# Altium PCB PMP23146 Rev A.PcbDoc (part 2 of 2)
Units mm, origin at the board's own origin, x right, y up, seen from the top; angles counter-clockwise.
Board outline 35 x 30 mm, 4 copper layers (Top Layer, Int1 (GND), Int2 (PWR), Bottom Layer), stack 0.912 mm thick; 72 components, 51 nets, 255 pads, 53 vias.
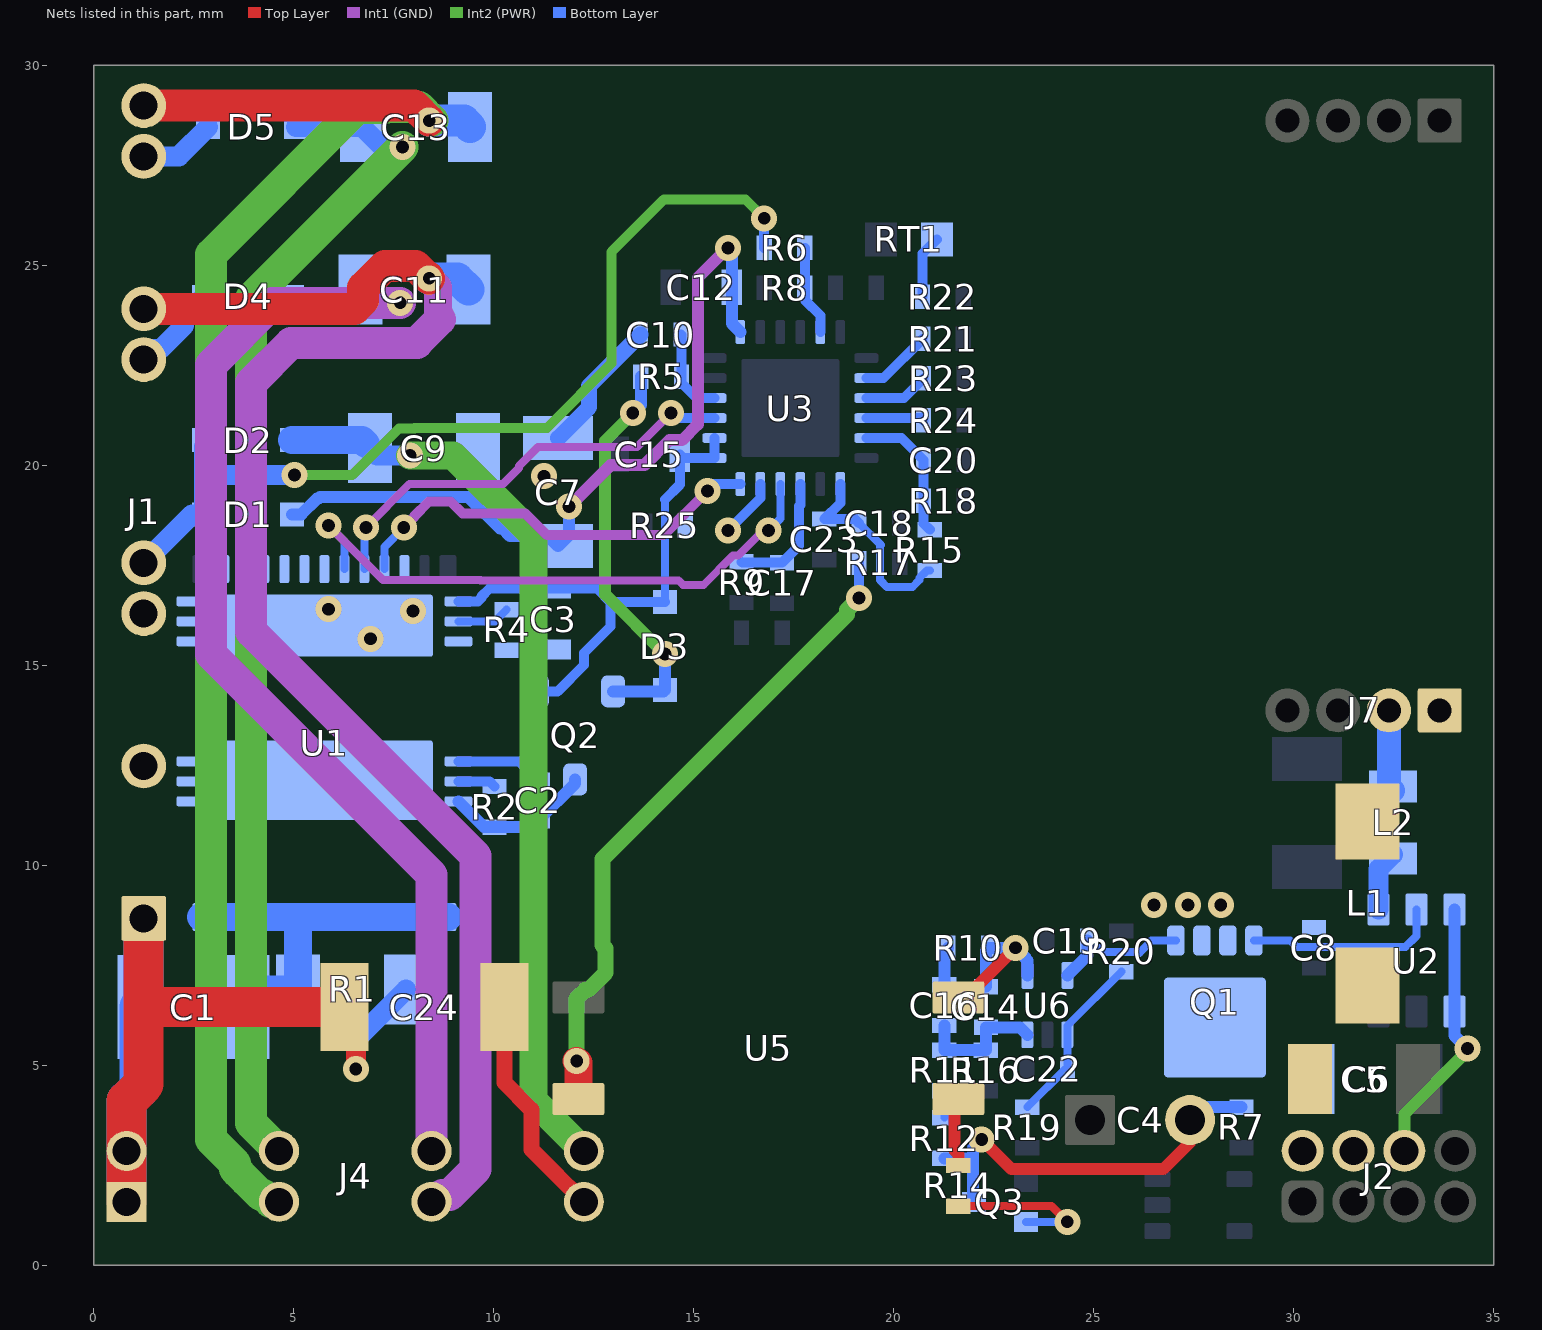
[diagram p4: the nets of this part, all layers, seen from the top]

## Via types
v1: diameter 0.65, hole 0.32, Top Layer to Bottom Layer, 44 vias
v2: diameter 0.5, hole 0.2, Top Layer to Bottom Layer, 5 vias
v3: diameter 0.65, hole 0.32, Top Layer to Bottom Layer, tented bottom, 4 vias

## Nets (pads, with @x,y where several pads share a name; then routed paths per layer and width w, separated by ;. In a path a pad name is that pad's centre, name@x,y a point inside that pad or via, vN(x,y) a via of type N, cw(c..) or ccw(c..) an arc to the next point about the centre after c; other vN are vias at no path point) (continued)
NetC1_2: C1.2 R1.1 U1.1 U1.2 U1.3 U1.4 U1.5 U1.6 U1.7 U1.8 U1.9 U1.10 U1.11 U1.12 U1.13 | length 9.5
  Bottom Layer w0.7: U1.13@2.673,8.707 U1.12@3.261,8.707 U1.11@3.761,8.707 U1.10@4.261,8.707 U1.9@4.761,8.707 U1.8@5.261,8.707 ; C1.2@3.837,6.46 4.276,6.899 R1.1@5.107,6.899 5.107,8.553 U1.8@5.261,8.707 ; U1.1@8.848,8.707 U1.2@8.261,8.707 U1.3@7.761,8.707 U1.4@7.261,8.707 U1.5@6.761,8.707 U1.6@6.261,8.707 U1.7@5.761,8.707 U1.8@5.261,8.707
NetC2_1: C2.1 U1.36 | length 2.2
  Bottom Layer w0.25: U1.36@9.111,12.602 10.628,12.602 C2.1@11.099,12.131
NetC14_1: C14.1 R10.2 U5.3 U6.4 | length 4.4
  Top Layer w0.3: U5.3@21.61,6.699 21.797,6.699 v1(23.039,7.941)
  Bottom Layer w0.3: C14.1@22.3,6.968 22.3,7.873 R10.2@22.369,7.941 v1(23.039,7.941) 23.286,7.695 23.286,7.673 23.334,7.624 U6.4@23.334,7.246
NetC14_2: C14.2 C16.1 R11.2 R16.2 U6.3 | length 3.3
  Bottom Layer w0.3: C16.1@21.26,5.998 R11.2@21.26,5.382 R16.2@22.297,5.382 22.297,5.574 ; R16.2@22.299,5.572 22.297,5.574 ; U6.3@23.334,5.766 23.149,5.952 C14.2@22.3,5.952 22.297,5.948 22.297,5.574
NetC16_2: C16.2 R10.1 | length 1
  Bottom Layer w0.3: C16.2@21.26,7.014 21.26,7.849 R10.1@21.353,7.941
NetC17_1: C17.1 R9.2 U3.9 | length 3.2
  Bottom Layer w0.25: R9.2@16.19,17.591 16.212,17.569 C17.1@17.202,17.569 17.63,17.997 17.63,18.982 17.661,19.013 U3.9@17.661,19.534
NetC20_2: C20.2 R15.1 R18.2 U3.5 | length 3.5
  Bottom Layer w0.25: U3.5@19.311,20.684 20.191,20.684 C20.2@20.741,20.134 R18.2@20.741,19.119 20.741,18.55 R15.1@20.899,18.392
NetC22_1: C22.1 R19.1 R20.2 U6.1 | length 4.4
  Bottom Layer w0.2: R19.1@23.334,3.957 24.288,4.911 C22.1@24.342,4.911 24.342,5.758 U6.1@24.334,5.766 24.334,5.991 R20.2@25.686,7.342
NetD3_1: D3.1 Q2.2 R5.2 | length 10.1
  Int2 (PWR) w0.3: v1(13.47,21.307) 12.78,20.617 12.78,16.778 v1(14.276,15.282)
  Bottom Layer w0.3: Q2.2@12.981,14.35 14.245,14.35 D3.1@14.276,14.381 v1(14.276,15.282) ; v1(13.47,21.307) 13.672,21.509 R5.2@13.672,22.218
NetD4_2: D4.2 J1.12 | length 2.3
  Bottom Layer w0.5: J1.12@1.245,22.646 1.505,22.906 1.663,22.906 2.255,23.498 2.255,23.714 D4.2@2.757,24.216
NetD5_2: D5.2 J1.16 | length 1.9
  Bottom Layer w0.5: J1.16@1.245,27.726 2.124,27.726 D5.2@2.857,28.46
NetJ7_1: J7.1 J7.2 L1.1 L2.1 | length 2
  Bottom Layer w0.6: J7.2@32.375,13.875 32.375,11.975 L2.1@32.477,11.873
NetQ1_4: Q1.4 U2.5 | length 4.9
  Bottom Layer w0.2: Q1.4@29,8.122 29.907,8.122 30.071,7.959 32.784,7.959 33.062,8.237 U2.5@33.062,8.897
NetQ3_2: Q3.2 R14.2 | length 3.9
  Top Layer w0.2: R14.2@21.61,1.482 23.942,1.482 v3(24.334,1.09)
  Bottom Layer w0.2: Q3.2@23.298,1.09 v3(24.334,1.09)
NetR2_2: R2.2 U1.37 | length 1
  Bottom Layer w0.25: U1.37@9.111,12.102 9.886,12.102 R2.2@10.015,11.973
NetR4_2: R4.2 U1.34 | length 1.3
  Bottom Layer w0.2: U1.34@9.111,16.102 10.023,16.102 R4.2@10.315,16.393
NetR6_1: R6.1 R8.2 U3.23 | length 2.3
  Bottom Layer w0.25: R6.1@17.772,25.438 R8.2@17.772,24.444 17.772,24.136 18.161,23.747 U3.23@18.161,23.334
NetR11_1: R11.1 R12.2 | length 0.7
  Bottom Layer w0.2: R12.2@21.26,3.692 R11.1@21.26,4.366
NetR14_1: R14.1 U5.1 | length 1.7
  Top Layer w0.3: R14.1@21.61,2.498 21.61,2.777 21.519,2.868 21.519,4.068 U5.1@21.61,4.159
NetR17_2: R17.2 U5.6 | length 16.5
  Top Layer w0.7: v1(12.069,5.11) 12.11,5.069 U5.6@12.11,4.159
  Int2 (PWR) w0.4: v1(12.069,5.11) 12.069,6.674 12.293,6.897 12.37,6.897 12.794,7.322 12.794,7.923 12.712,8.005 12.712,10.157 18.831,16.276 18.831,16.39 v1(19.128,16.687)
  Bottom Layer w0.25: v1(19.128,16.687) R17.2@19.128,17.561
NetR21_2: R21.2 U3.2 | length 1.8
  Bottom Layer w0.25: U3.2@19.311,22.184 19.741,22.184 R21.2@20.719,23.162
NetR22_2: R22.2 RT1.2 | length 1.6
  Bottom Layer w0.25: R22.2@20.716,24.216 20.716,25.295 RT1.2@21.075,25.654
NetR23_2: R23.2 U3.3 | length 1.6
  Bottom Layer w0.25: U3.3@19.311,21.684 20.25,21.684 R23.2@20.741,22.176
NetR24_2: R24.2 U3.4 | length 1.5
  Bottom Layer w0.25: U3.4@19.311,21.184 20.686,21.184 R24.2@20.741,21.129
P12V: C9.1 D2.1 J4.20 | length 22.9
  Int2 (PWR) w0.7: v1(7.904,20.25) 8.981,20.25 10.984,18.247 10.984,4.123 J4.20@12.247,2.86
  Bottom Layer w0.5: C9.1@6.798,20.533 C9.1@6.896,20.434 7.08,20.25 v1(7.904,20.25)
  Bottom Layer w0.7: D2.1@4.957,20.632 5.373,20.633 6.698,20.632 C9.1@6.798,20.533
P12V_ISO1: C13.1 D5.1 J4.8 | length 29.8
  Int2 (PWR) w0.8: J4.8@4.627,2.86 3.924,3.563 3.924,24.173 v3(7.711,27.96)
  Bottom Layer w0.5: D5.1@5.057,28.46 C13.1@6.707,28.46 7.207,27.96 v3(7.711,27.96)
P12V_ISO1_RTN: C13.2 J1.17 J4.7 | length 40.2
  Top Layer w0.8: J1.17@1.245,28.996 8.002,28.996 v1(8.382,28.617)
  Int2 (PWR) w0.7: v1@8.389,28.625 8.397,28.617 v1@8.468,28.617
  Int2 (PWR) w0.8: J4.7@4.627,1.59 4.408,1.59 4.238,1.76 4.172,1.76 3.804,2.128 3.658,2.273 3.595,2.337 3.535,2.397 3.527,2.404 3.527,2.546 2.924,3.149 2.924,25.268 6.597,28.941 7.278,28.941 7.296,28.96 8.125,28.96 v1@8.468,28.617
  Bottom Layer w0.8: v1(8.382,28.617) 9.25,28.617 C13.2@9.407,28.46
P12V_ISO2: C11.1 D4.1 J4.14 | length 30.4
  Top Layer w0.2: J4.14@8.23,2.848 8.425,2.848 J4.14@8.437,2.86
  Int1 (GND) w0.8: v1(7.657,24.066) 4.48,24.066 2.924,22.511 2.924,15.28 8.437,9.767 J4.14@8.437,2.86
  Bottom Layer w0.5: D4.1@4.957,24.216 6.484,24.216 C11.1@6.665,24.397 6.995,24.066 v1(7.657,24.066)
P12V_ISO2_RTN: C11.2 J1.13 J4.13 | length 39.2
  Top Layer w0.2: J4.13@8.234,1.59 J4.13@8.437,1.59
  Top Layer w0.8: J1.13@1.245,23.916 6.515,23.916 6.732,24.134 6.732,24.449 7.274,24.991 8.04,24.991 8.325,24.707 8.352,24.707 v1(8.382,24.677)
  Int1 (GND) w0.7: v1@8.343,24.724 8.607,24.46 8.607,23.804 8.657,23.754 8.657,23.652
  Int1 (GND) w0.8: J4.13@8.437,1.59 8.543,1.59 8.713,1.76 8.893,1.76 9.537,2.404 9.537,10.239 3.924,15.852 3.924,22.06 4.931,23.066 8.071,23.066 8.657,23.652
  Bottom Layer w0.8: v1(8.382,24.677) 9.085,24.677 C11.2@9.365,24.397
P13: C3.2 C15.2 D3.2 Q2.1 U1.33 U3.13 U3.14 | length 14
  Bottom Layer w0.2: D3.2@14.276,16.581 14.276,19.146
  Bottom Layer w0.25: U1.33@9.111,16.602 9.598,16.602 9.685,16.689 9.685,16.719 9.889,16.922 C3.2@11.484,16.922 12.573,16.922 12.915,16.581 ; Q2.1@11.081,14.35 11.594,14.35 12.254,15.01 12.254,15.31 12.915,15.971 12.915,16.581 ; D3.2@14.276,16.581 12.915,16.581 ; 14.276,19.146 14.648,19.518 C15.2@14.648,20.274 14.738,20.184 U3.13@15.511,20.184 U3.14@15.511,20.684
PWMH: U1.28 U3.15 | length 11
  Int1 (GND) w0.2: v1(6.798,18.449) 7.883,19.534 10.225,19.534 10.628,19.937 10.628,19.988 11.099,20.459 13.576,20.459 v1(14.424,21.307)
  Bottom Layer w0.2: U1.28@6.761,17.407 6.761,18.412 v1(6.798,18.449)
  Bottom Layer w0.25: v1(14.424,21.307) 14.547,21.184 U3.15@15.511,21.184
PWML: U1.29 U3.12 | length 10.8
  Int1 (GND) w0.25: v1(7.746,18.449) 7.996,18.699 7.996,18.719 8.377,19.099 8.915,19.099 9.212,18.803 10.779,18.803 11.327,18.255 14.232,18.255 v1(15.336,19.359)
  Bottom Layer w0.2: U1.29@7.261,17.407 7.261,17.964 v1(7.746,18.449)
  Bottom Layer w0.25: v1(15.336,19.359) 15.511,19.534 U3.12@16.161,19.534
PWRGND: C3.1 C7.2 C9.2 C10.1 C24.2 J1.7 J4.19 R4.1 R25.1 U1.17 U1.18 U1.19 U1.21 U1.22 U1.23 U1.24 U1.25 U1.26 U1.30 U1.35 U1.40 U3.11 | length 10.6
  Top Layer w0.4: C24.2@10.261,6.46 10.258,6.457 10.258,4.575 10.937,3.896 10.937,2.9 11.347,2.49 11.347,2.487 11.874,1.96 11.877,1.96 J4.19@12.247,1.59
  Bottom Layer w0.25: v1(15.848,18.37) 16.661,19.183 U3.11@16.661,19.534
  Bottom Layer w0.4: C7.2@11.603,20.679 12.378,21.454 12.378,21.988 C10.1@13.662,23.272
  other v1: 6.911,15.666 7.977,16.361 5.861,16.404 11.253,19.729
REF: C18.2 C23.1 R15.2 U3.7 | length 5.1
  Bottom Layer w0.2: C18.2@19.128,18.555 19.674,18.01 19.654,17.99 19.654,17.132 19.829,16.956 20.459,16.956 20.635,17.132 20.635,17.184 20.827,17.376 R15.2@20.899,17.376
  Bottom Layer w0.25: U3.7@18.661,19.534 18.661,19.058 C23.1@18.26,18.657 19.026,18.657 C18.2@19.128,18.555
RUN: U1.27 U3.10 | length 14.7
  Int1 (GND) w0.2: v3(5.861,18.499) 7.228,17.132 9.662,17.132 9.666,17.128 14.615,17.128 14.727,17.016 15.245,17.016 15.974,17.745 16.107,17.745 16.732,18.37 v1(16.86,18.37)
  Bottom Layer w0.2: v3(5.861,18.499) 6.261,18.099 U1.27@6.261,17.407 ; v1(16.86,18.37) 17.161,18.671 U3.10@17.161,19.534
SWS: C10.2 R5.1 U3.16 | length 2.2
  Bottom Layer w0.25: C10.2@14.678,23.272 14.688,23.262 R5.1@14.688,22.218 14.688,22.06 15.063,21.684 U3.16@15.511,21.684
VAUX: D1.2 D2.2 J1.8 R6.2 | length 23.3
  Int2 (PWR) w0.25: v3(5.011,19.758) 6.457,19.758 7.624,20.925 8.009,20.925 8.018,20.934 11.325,20.934 12.942,22.552 12.942,25.34 14.246,26.645 14.34,26.645 14.341,26.646 16.289,26.646 v1(16.756,26.179)
  Bottom Layer w0.25: R6.2@16.756,25.438 v1(16.756,26.179)
  Bottom Layer w0.5: J1.8@1.245,17.566 2.448,18.769 D1.2@2.757,18.769 2.757,19.858 ; D2.2@2.811,20.533 2.757,20.479 2.757,19.858 ; v3(5.011,19.758) 2.857,19.758 2.757,19.858
VDCIN: C1.1 C24.1 J1.1 J4.1 J4.2 R1.2 | length 23.8
  Top Layer w0.5: C24.1@6.261,6.46 6.546,6.174 v1(6.546,4.911)
  Top Layer w1: J4.1@0.817,1.59 J4.2@0.817,2.86 0.817,4.104 1.245,4.532 1.245,6.46 ; J1.1@1.245,8.676 1.245,6.46 ; 1.305,6.399 1.245,6.46 ; C24.1@6.261,6.46 1.245,6.46
  Bottom Layer w0.5: v1(6.546,4.911) 6.546,5.638 R1.2@7.807,6.899
  Bottom Layer w1: J4.1@0.817,1.59 J4.2@0.817,2.86 0.817,4.104 1.137,4.424 C1.1@1.137,6.46 1.245,6.568 J1.1@1.245,8.676
VDD: C7.1 C12.1 D1.1 U3.19 | length 19.5
  Int1 (GND) w0.3: v1(11.877,18.969) 12.917,20.009 13.763,20.009 14.385,20.632 14.704,20.632 15.099,21.028 15.099,24.689 v1(15.848,25.438)
  Bottom Layer w0.3: D1.1@4.957,18.769 5.186,18.769 5.186,18.779 5.581,19.174 5.611,19.174 5.646,19.209 9.365,19.209 10.146,18.428 10.204,18.428 10.402,18.23 11.352,18.23 C7.1@11.603,17.979 11.877,18.253 v1(11.877,18.969) ; v1(15.848,25.438) 15.948,25.338 C12.1@15.948,24.449 15.948,23.547 U3.19@16.161,23.334
VOUT: C4.2 C5.2 C8.1 C19.2 J2.2 L1.2 L2.2 Q1.1 Q1.2 Q1.3 Q3.3 R7.2 R12.1 U2.4 U6.5 | length 15.2
  Top Layer w0.3: v1(22.194,3.147) 22.937,2.404 26.732,2.404 27.403,3.076 C4.2@27.403,3.636
  Bottom Layer w0.2: C19.2@24.842,7.938 25.151,7.938 25.257,7.833 26.115,7.833 26.134,7.813 26.443,8.122 Q1.1@27.05,8.122
  Bottom Layer w0.3: R12.1@21.26,2.676 21.966,2.676 21.978,2.689 ; Q3.3@21.998,1.59 21.978,1.61 21.978,2.689 ; v1(22.194,3.147) 21.978,2.931 21.978,2.689 ; U6.5@24.334,7.246 24.842,7.754 24.842,7.938 C19.2@24.842,8.122 ; C4.2@27.303,3.736 27.524,3.957 R7.2@28.688,3.957
  Bottom Layer w0.5: U2.4@32.112,8.897 32.112,9.908 L2.2@32.477,10.273
  other v1: 26.501,9.007 27.348,9.007 28.171,9.007
VOUT_OR: C6.1 J2.4 J2.6 Q1.5 Q1.6 Q1.7 Q1.8 Q1.9@28.025,5.947 U2.1 U2.6 | length 6.8
  Int2 (PWR) w0.3: J2.6@32.758,2.866 32.758,3.782 34.339,5.363 v1(34.339,5.419)
  Bottom Layer w0.3: U2.6@34.012,8.897 U2.1@34.012,6.347 34.012,5.746 v1(34.339,5.419)
VSWN: C2.2 J1.4 Q2.3 R2.1 U1.14 U1.15 U1.16 U1.38 U1.39 | length 3.7
  Bottom Layer w0.3: U1.38@9.111,11.602 9.755,10.957 R2.1@10.015,10.957 10.941,10.957 C2.2@11.099,11.115 12.031,12.047 Q2.3@12.031,12.15
pads on no net: Q1.9@27.05,5.422 Q1.9@27.7,5.422 Q1.9@27.363,5.933 Q1.9@27.363,6.809 Q1.9@28.025,6.27 Q1.9@28.35,5.422 Q1.9@28.688,5.933 Q1.9@28.688,6.809 Q1.9@29,5.422 U1.20 U2.3 U4.2 U4.4 U4.5

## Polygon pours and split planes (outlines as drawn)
GND on Bottom Layer "BOTTOM_LAYER_GND_P013" (solid, remove dead copper, pour order 13): 27.041,11.312 27.041,9.306 31.306,9.306 31.306,11.312
GND on Bottom Layer "BOTTOM_LAYER_GND_P012" (solid, remove dead copper, pour order 12): 20.974,8.287 20.974,0.13 34.957,0.13 34.957,8.287
VOUT on Bottom Layer "BOTTOM_LAYER_VOUT_P011" (solid, remove dead copper, pour order 11): 26.167,9.432 26.167,7.246 32.503,7.246 32.503,9.432
VOUT_OR on Bottom Layer "BOTTOM_LAYER_VOUT_OR_P006" (solid, remove dead copper, pour order 6): 26.663,7.263 26.663,2.246 33.452,2.246 33.452,7.263
ICGND on Bottom Layer "BOTTOM_LAYER_ICGND_P002" (solid, remove dead copper, pour order 2): 12.786,26.454 12.786,15.466 22.328,15.466 22.328,26.454
VSWN on Bottom Layer "BOTTOM_LAYER_VSWN_P001" (solid, remove dead copper, pour order 1): 0.635,13.15 0.635,11.073 9.665,11.073 9.665,13.15
PWRGND on Bottom Layer "BOTTOM_LAYER_PWRGND_P000" (solid, remove dead copper, pour order 0): 0.384,22.414 0.384,15.251 22.328,15.251 22.328,22.414
NetJ7_1 on Top Layer "TOP_LAYER_NETJ7_1_P008" (solid, remove dead copper, pour order 8): 28.95,14.423 28.95,10.157 35,10.157 35,14.423
GND on Top Layer "TOP_LAYER_GND_P014" (solid, remove dead copper, pour order 14): 20.993,8.272 20.993,0.116 34.976,0.116 34.976,8.272
VOUT on Top Layer "TOP_LAYER_VOUT_P007" (solid, remove dead copper, pour order 7): 26.053,9.397 26.053,2.225 35,2.225 35,9.397
PWRGND on Top Layer "TOP_LAYER_PWRGND_P005" (solid, remove dead copper, pour order 5): 11.877,26.455 11.877,15.467 22.365,15.467 22.365,26.455
PWRGND on Top Layer "TOP_LAYER_PWRGND_P003" (solid, remove dead copper, pour order 3): 0.089,21.334 0.089,-0.008 12.712,-0.008 12.712,21.334
GND on Int2 (PWR) "INT2_(PWR)_GND_P018" (solid, remove dead copper, pour order 18): 20.974,11.602 20.974,0.262 34.867,0.262 34.867,11.602
ISNS on Int2 (PWR) "INT2_(PWR)_ISNS_P015" (solid, remove dead copper, pour order 15): 28.904,29.984 28.904,12.738 34.965,12.738 34.965,29.984
ICGND on Int2 (PWR) "INT2_(PWR)_ICGND_P004" (solid, remove dead copper, pour order 4): 12.786,26.454 12.786,15.466 22.328,15.466 22.328,26.454
GND on Int1 (GND) "INT1_(GND)_GND_P016" (solid, remove dead copper, pour order 16): 20.974,11.602 20.974,0 35,0 35,11.602
ISNS on Int1 (GND) "INT1_(GND)_ISNS_P010" (solid, remove dead copper, pour order 10): 28.95,30.051 28.95,12.805 35.012,12.805 35.012,30.051

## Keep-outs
Int1 (GND):
  lines w0.254: 20.993,8.632 22.918,8.632 26.277,12.003
Int2 (PWR):
  lines w0.254: 20.993,8.632 22.906,8.632 26.277,12.003
Keep-Out Layer:
  text ".Layer_Name" at 14.656,-21.806 h1.52

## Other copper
Top Layer:
  text ".Layer_Name" at 14.656,-21.806 h1.52
Bottom Layer:
  text ".Layer_Name" at 14.656,-21.806 h1.52

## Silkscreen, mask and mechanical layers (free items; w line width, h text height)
Top Overlay:
  text ".Layer_Name" at 14.656,-21.806 h1.52
Bottom Overlay:
  text "PMP23146PCB Rev A" at 29,28.11 h2
  text ".Layer_Name" at 14.656,-21.806 h1.52
Top Paste:
  text ".Layer_Name" at 14.656,-21.806 h1.52
Bottom Paste:
  text ".Layer_Name" at 14.656,-21.806 h1.52
Top Solder:
  text ".Layer_Name" at 14.656,-21.806 h1.52
  text ".Layer_Name" at 14.656,-21.806 h1.52
Bottom Solder:
  text ".Layer_Name" at 14.656,-21.806 h1.52
Drill Guide:
  text ".Layer_Name" at 14.656,-21.806 h1.52
M1 Board Outline:
  the board outline again, w0.254
  text ".Layer_Name" at 14.656,-21.806 h1.52
M2 Board Dimensions:
  rectangle: 0,-6.985 3.175,-3.81
  rectangle: 3.175,-10.16 12.7,-6.985
  lines w0.178: 0,-6.985 25.4,-6.985 ; 3.175,-10.16 3.175,-3.81 ; 6.35,-10.16 6.35,-3.81 ; 12.7,-10.16 12.7,-3.81 ; 19.05,-10.16 19.05,-3.81 ; 0,-10.16 25.4,-10.16 25.4,-3.81 0,-3.81 0,-10.16
  text ".Layer_Name" at 14.656,-21.806 h1.52
M3 3D STEP Top:
  text ".Layer_Name" at 14.656,-21.806 h1.52
M4 3D STEP Bottom:
  text ".Layer_Name" at 14.656,-21.806 h1.52
M5 Assembly Top:
  lines w0.254: -7.417,-23.626 160.223,-23.626 ; -7.417,-18.462 160.274,-18.462 ; -7.417,-13.297 -7.417,-28.791 94.31,-28.791 160.274,-28.791 160.274,-13.297 -7.404,-13.297 -7.404,-28.791 32.614,-28.791 ; 55.194,-28.791 55.194,-13.297 ; 87.376,-18.462 87.376,-13.297 ; 108.712,-18.462 108.712,-13.297 ; 124.511,-28.956 124.511,-23.804
  text "COMPONENTS MARKED 'DNP' SHOULD NOT BE POPULATED." at 29.299,-8.09 h1.52
  text "ASSEMBLY VARIANT:" at 29.286,-11.024 h1.52
  text ".VariantName" at 55.601,-11.024 h1.52
  text "PCB VIEWED FROM TOP SIDE" at -5.804,-16.654 h1.52
  text "BOARD #:" at 57.099,-16.654 h1.52
  text ".PRJ_Number" at 70.955,-16.654 h1.52
  text "REV:" at 92.405,-16.654 h1.52
  text ".PCB_Rev" at 99.809,-16.654 h1.52
  text "SVN REV:" at 113.69,-16.654 h1.52
  text ".VersionControl_RevNumber" at 126.543,-16.654 h1.52
  text "TID #:" at 57.099,-21.819 h1.52
  text ".TID" at 70.955,-21.819 h1.52
  text "PLOT NAME =" at -5.804,-27.034 h1.52
  text ".plot_File_Name" at 14.656,-27.034 h1.52
  text "GENERATED    :" at 57.15,-27.034 h1.52
  text ".Print_Date" at 79.235,-27.034 h1.52
  text ".Print_Time" at 97.752,-27.034 h1.52
  text "TEXAS INSTRUMENTS" at 129.87,-27.034 h1.52
M6 Assembly Bottom:
  lines w0.254: -7.429,-18.474 160.261,-18.474 ; -7.379,-23.639 160.261,-23.639 ; 28.334,-28.969 28.334,-23.817 ; 44.133,-18.474 44.133,-13.31 ; 65.468,-18.474 65.468,-13.31 ; 97.65,-28.804 97.65,-13.31 ; 120.231,-28.804 160.249,-28.804 160.249,-13.31 -7.429,-13.31 -7.429,-28.804 58.534,-28.804 160.261,-28.804 160.261,-13.31
  text "COMPONENTS MARKED 'DNP' SHOULD NOT BE POPULATED." at 154.991,-8.077 h1.52
  text ".VariantName" at 128.473,-11.024 h1.52
  text "ASSEMBLY VARIANT:" at 154.864,-11.024 h1.52
  text ".VersionControl_RevNumber" at 26.302,-16.667 h1.52
  text "SVN REV:" at 39.154,-16.667 h1.52
  text ".PCB_Rev" at 53.035,-16.667 h1.52
  text "REV:" at 60.439,-16.667 h1.52
  text ".PRJ_Number" at 81.89,-16.667 h1.52
  text "BOARD #:" at 95.745,-16.667 h1.52
  text "PCB VIEWED FROM BOTTOM SIDE" at 158.648,-16.667 h1.52
  text ".TID" at 81.89,-21.831 h1.52
  text "TID #:" at 95.745,-21.831 h1.52
  text "TEXAS INSTRUMENTS" at 22.974,-27.047 h1.52
  text ".Print_Time" at 55.093,-27.047 h1.52
  text ".Print_Date" at 73.609,-27.047 h1.52
  text "GENERATED    :" at 95.694,-27.047 h1.52
  text ".plot_File_Name" at 138.189,-27.047 h1.52
  text "PLOT NAME =" at 158.648,-27.047 h1.52
M9 Title Sheet:
  drawing of 57 lines, arcs and shapes, not listed
  text "1" at 18.792,204.127 h1.78
  text "2" at 82.182,204.127 h1.78
  text "3" at 145.411,204.127 h1.78
  text "4" at 209.08,204.127 h1.78
  text "5" at 272.555,204.127 h1.78
  text "6" at 336.182,204.127 h1.78
  text "A" at -10.579,175.095 h1.78
  text "A" at 365.341,175.095 h1.78
  text "B" at -10.579,114.643 h1.78
  text "B" at 365.341,114.643 h1.78
  text "C" at -10.579,54.318 h1.78
  text "C" at 365.341,54.318 h1.78
  text "PROJECT TITLE:" at 288.125,7.048 h1.14
  text ".PRJ_Title" at 289.395,3.662 h1.78
  text "DESIGNED FOR:" at 288.125,-0.597 h1.14
  text ".PRJ_Customer" at 289.395,-4.153 h1.78
  text "D" at -10.579,-5.88 h1.78
  text "D" at 365.341,-5.88 h1.78
  text "FILE NAME:" at 288.125,-8.217 h1.14
  text ".PCB_File_Name_No_Path" at 289.395,-11.265 h1.78
  text "Texas Instruments (TI) and/or its licensors do not warrant the accuracy or completeness of this specification" at 161.9,-15.376 h1.14
  text "ENGINEER:" at 288.125,-15.583 h1.14
  text "LAYOUT BY:" at 326.352,-15.583 h1.14
  text "or any information contained therein. TI and/or its licensors do not warrant that this design will meet" at 160.757,-18.237 h1.14
  text ".PRJ_Engineer" at 289.395,-19.52 h1.78
  text ".PCB_Layout" at 327.635,-19.52 h1.78
  text "the specifications, will be suitable for your application or fit for any particular purpose, or will operate in" at 160.757,-21.099 h1.14
  text ".Layer_Name" at 14.656,-21.806 h1.52
  text "ALTIUM DESIGNER VERSION:" at 326.352,-23.457 h1.14
  text "an implementation. TI and/or its licensors do not warrant that the design is production worthy. You should" at 160.757,-23.961 h1.14
  text "completely validate and test your design implementation to confirm the system functionality for your application." at 161.9,-26.822 h1.14
  text ".print_Scale" at 289.395,-26.843 h1.78
  text ".Application_BuildNumber" at 327.635,-26.843 h1.78
  text "1" at 18.792,-32.093 h1.78
  text "2" at 82.182,-32.093 h1.78
  text "3" at 145.411,-32.093 h1.78
  text "4" at 209.08,-32.093 h1.78
  text "5" at 272.555,-32.093 h1.78
  text "6" at 336.182,-32.093 h1.78
M10 Fab Notes:
  drawing of 189 lines, arcs and shapes, not listed
  text "DESIGN INFORMATION" at 314.503,161.447 h1.52
  text "MIN. TRACK WIDTH:" at 298.131,158.091 h1.52
  text "8" at 325.976,158.091 h1.52
  text "MIL" at 329.907,158.091 h1.52
  text "7.874" at 321.75,155 h1.52
  text "MIN. CLEARANCE:" at 298.131,154.938 h1.52
  text "MIL" at 329.907,154.938 h1.52
  text "MIN. VIA PAD SIZE:" at 298.131,151.785 h1.52
  text "24" at 325.214,151.785 h1.52
  text "MIL" at 329.907,151.785 h1.52
  text "0.05mm (2MIL)" at 315.784,148.486 h1.52
  text "MINIMUM ANNULAR RING" at 289.769,148.277 h1.52
  text "EXTERNAL" at 333.768,148.277 h1.52
  text "PER" at 294.849,145.48 h1.52
  text "IPC-D-275 CLASS 2 LEVEL C" at 300.437,145.48 h1.52
  text "MIL, HOLES" at 338.238,142.928 h1.52
  text "+/-" at 328.27,142.709 h1.52
  text "+/-" at 349.961,142.709 h1.52
  text "REGISTRATION TOLERANCES:" at 289.769,142.682 h1.52
  text "METAL" at 320.243,142.682 h1.52
  text "5" at 334.879,142.683 h1.52
  text "3" at 356.037,142.683 h1.52
  text "MIL" at 358.99,142.682 h1.52
  text "HOLE SIZE TOLERANCE (UNLESS OTHERWISE SPECIFIED):" at 289.769,140.185 h1.52
  text "+/-" at 349.961,140.112 h1.52
  text "3" at 356.037,140.085 h1.52
  text "MIL" at 358.99,140.085 h1.52
  text "MATERIAL:" at 287.87,136.589 h1.52
  text "FR-4 High Tg" at 312.926,133.324 h1.52
  text "X" at 309.257,133.122 h1.52
  text "FR-408" at 298.563,133.007 h1.52
  text "OTHER" at 336.358,133.007 h1.52
  text "62 MIL (1.6mm) +/-10%" at 306.694,129.374 h1.52
  text "X" at 303.643,129.312 h1.52
  text "THICKNESS:" at 289.769,129.165 h1.52
  text "OTHER" at 339.33,129.165 h1.52
  text "TOLERANCE:" at 289.769,125.652 h1.52
  text "X" at 311.314,125.652 h1.52
  text "ANSI IPC-6012 TYPE 3 CLASS 2" at 315.836,125.652 h1.52
  text "OTHER +/-" at 315.835,121.989 h1.52
  text "BOW & TWIST:" at 289.769,118.302 h1.52
  text "X" at 311.314,118.302 h1.52
  text "ANSI IPC-6012 TYPE 3 CLASS 2" at 315.836,118.302 h1.52
  text "OTHER +/-" at 315.835,114.576 h1.52
  text "DRILLING:" at 287.87,111.258 h1.52
  text "NC_DRILL FILES" at 332.599,108.586 h1.52
  text "REFERENCE:" at 289.769,108.486 h1.52
  text "X" at 306.463,108.484 h1.52
  text "AS SHOWN" at 310.984,108.486 h1.52
  text "X" at 329.348,108.486 h1.52
  text "OTHER" at 340.168,104.873 h1.52
  text "PTH COPPER THICKNESS:" at 289.761,104.783 h1.52
  text "X" at 318.697,104.783 h1.52
  text "20-30 um" at 321.948,104.783 h1.52
  text "BOARD FINISH:" at 287.87,101.034 h1.52
  text "SILKSCREEN:" at 291.812,98.237 h1.52
  text "X" at 316.14,98.237 h1.52
  text "TOP" at 319.112,98.237 h1.52
  text "X" at 329.094,98.237 h1.52
  text "BOTTOM" at 332.091,98.237 h1.52
  text "SILKSCREEN COLOR:" at 291.812,94.295 h1.52
  text "X" at 316.115,94.295 h1.52
  text "WHITE" at 319.112,94.295 h1.52
  text "OTHER" at 332.091,94.295 h1.52
  text "X" at 319.442,90.652 h1.52
  text "GREEN" at 322.439,90.652 h1.52
  text "OTHER" at 338.136,90.652 h1.52
  text "SOLDER RESIST COLOR:" at 291.812,90.477 h1.52
  text "X" at 319.442,86.734 h1.52
  text "MATTE" at 322.439,86.734 h1.52
  text "SEMI-GLOSS" at 338.125,86.717 h1.52
  text "IMMERSION GOLD (ENIG)" at 314.819,82.345 h1.52
  text "ENEPIG" at 348.793,82.162 h1.52
  text "SURFACE FINISH:" at 287.87,82.136 h1.52
  text "X" at 310.298,82.136 h1.52
  text "IMM. TIN/SILVER OR EQUIV" at 296.24,78.649 h1.52
  text "OTHER" at 332.599,78.549 h1.52
  text "ARRAY/PANEL:" at 287.87,74.602 h1.52
  text "CUT AND TRIM PER M1 BOARD OUTLINE" at 314.819,74.393 h1.52
  text "N.C. ROUTE" at 314.819,70.94 h1.52
  text "X" at 332.295,70.94 h1.52
  text "V. SCORE" at 336.816,70.94 h1.52
  text "CERTIFICATION:" at 287.87,67.66 h1.52
  text "MATERIALS AND WORKMANSHIP FOR ALL PCBS" at 306.285,67.66 h1.52
  text "TO MEET OR EXCEED THE REQUIREMENTS OF:" at 306.285,65.271 h1.52
  text "X" at 297.078,62.003 h1.52
  text "ANSI IPC-A-600F CLASS ->" at 300.329,62.003 h1.52
  text "X" at 342.188,62.003 h1.52
  text "2" at 344.982,62.003 h1.52
  text "1" at 336.981,61.965 h1.52
  text "3" at 353.973,61.965 h1.52
  text "X" at 317.702,58.252 h1.52
  text "RoHS" at 320.953,58.252 h1.52
  text "OTHER" at 337.321,58.252 h1.52
  text "PER ORDER" at 347.407,58.252 h1.52
  text "ALL BOARDS MUST MEET OR EXCEED UL94-V0 REQUIREMENTS." at 288.569,54.345 h1.52
  text "PCB MUST BEAR THE UL94V-0 UL REGISTERED MATERIAL ID NUMBER" at 288.569,51.397 h1.52
  text "ADDITIONAL REQUIREMENTS:" at 287.87,47.094 h1.52
  text "MICROSECTION:" at 289.769,44.373 h1.52
  text "YES" at 312.775,44.373 h1.52
  text "REQUIRED" at 334.657,40.707 h1.52
  text "BARE BOARD ELEC. TEST:" at 289.769,40.634 h1.52
  text "NONE" at 322.935,40.634 h1.52
  text "X" at 331.66,40.634 h1.52
  text "PER ORDER" at 349.693,40.634 h1.52
  text "XX MIL VIAS REQUIRE NON-CONDUCTIVE FILL AND PLANARIZE" at 294.04,35.428 h1.5
  text "XX MIL VIAS REQUIRE CONDUCTIVE FILL AND PLANARIZE" at 294.243,32.787 h1.52
  text "OUTER XX MIL TRACES REQUIRE 50 OHM SINGLE-ENDED IMPEDANCE" at 294.218,28.637 h1.47
  text "LAYER 2 & 3 (INNER LAYERS) XX MIL WIDE, XX MIL SPACE / TRACES REQUIRE 100 OHM DIFFERENTIAL IMPEDANCE" at 294.015,22.65 h1.52
  text ".Layer_Name" at 14.656,-21.806 h1.52
M11 Gerber Information:
  lines w0.254: -7.417,-23.626 160.223,-23.626 ; -7.417,-18.462 160.274,-18.462 ; -7.417,-13.297 -7.417,-28.791 94.31,-28.791 160.274,-28.791 160.274,-13.297 -7.404,-13.297 -7.404,-28.791 32.614,-28.791 ; 55.194,-28.791 55.194,-13.297 ; 87.376,-18.462 87.376,-13.297 ; 108.712,-18.462 108.712,-13.297 ; 124.511,-28.956 124.511,-23.804
  text "ALL ARTWORK VIEWED FROM TOP SIDE" at -5.804,-16.654 h1.52
  text "BOARD #:" at 57.099,-16.654 h1.52
  text ".PRJ_Number" at 70.955,-16.654 h1.52
  text "REV:" at 92.405,-16.654 h1.52
  text ".PCB_Rev" at 99.809,-16.654 h1.52
  text "SVN REV:" at 113.69,-16.654 h1.52
  text ".VersionControl_RevNumber" at 126.543,-16.654 h1.52
  text "LAYER NAME =" at -5.804,-21.806 h1.52
  text "TID #:" at 57.099,-21.819 h1.52
  text ".TID" at 70.955,-21.819 h1.52
  text "PLOT NAME =" at -5.804,-27.034 h1.52
  text ".plot_File_Name" at 14.656,-27.034 h1.52
  text "GENERATED    :" at 57.15,-27.034 h1.52
  text ".Print_Date" at 79.235,-27.034 h1.52
  text ".Print_Time" at 97.752,-27.034 h1.52
  text "TEXAS INSTRUMENTS" at 129.87,-27.034 h1.52
M12 Stackup:
  drawing of 399 lines, arcs and shapes, not listed
  text "Layer" at 249.469,200.023 h1.52
  text "Name" at 259.88,200.023 h1.52
  text "Material" at 293.653,200.023 h1.52
  text "Thickness" at 308.889,200.023 h1.52
  text "Constant" at 325.395,200.023 h1.52
  text "Board Layer Stack" at 339.869,200.023 h1.52
  text "Top Overlay" at 259.88,196.975 h1.52
  text "Top Solder" at 259.88,193.927 h1.52
  text "SM-001" at 293.653,193.927 h1.52
  text "1.00mil" at 308.889,193.927 h1.52
  text "4" at 325.395,193.927 h1.52
  text "Top Surface Finish" at 259.88,190.879 h1.52
  text "PbSn" at 293.653,190.879 h1.52
  text "0.79mil" at 308.889,190.879 h1.52
  text "1" at 249.469,187.831 h1.52
  text "Top Layer" at 259.88,187.831 h1.52
  text "CF-004" at 293.653,187.831 h1.52
  text "1.38mil" at 308.889,187.831 h1.52
  text "Dielectric 1" at 259.88,184.783 h1.52
  text "PP-017" at 293.653,184.783 h1.52
  text "5.10mil" at 308.889,184.783 h1.52
  text "4.3" at 325.395,184.783 h1.52
  text "Dielectric 2" at 259.88,181.735 h1.52
  text "PP-017" at 293.653,181.735 h1.52
  text "5.10mil" at 308.889,181.735 h1.52
  text "4.3" at 325.395,181.735 h1.52
  text "2" at 249.469,178.687 h1.52
  text "Int1 (GND)" at 259.88,178.687 h1.52
  text "CF-004" at 293.653,178.687 h1.52
  text "1.38mil" at 308.889,178.687 h1.52
  text "Dielectric 3" at 259.88,175.639 h1.52
  text "Core-028" at 293.653,175.639 h1.52
  text "10.00mil" at 308.889,175.639 h1.52
  text "4.3" at 325.395,175.639 h1.52
  text "3" at 249.469,172.591 h1.52
  text "Int2 (PWR)" at 259.88,172.591 h1.52
  text "CF-004" at 293.653,172.591 h1.52
  text "1.38mil" at 308.889,172.591 h1.52
  text "Dielectric 4" at 259.88,169.543 h1.52
  text "PP-017" at 293.653,169.543 h1.52
  text "5.10mil" at 308.889,169.543 h1.52
  text "4.3" at 325.395,169.543 h1.52
  text "Dielectric 5" at 259.88,166.495 h1.52
  text "PP-017" at 293.653,166.495 h1.52
  text "5.10mil" at 308.889,166.495 h1.52
  text "4.3" at 325.395,166.495 h1.52
  text "4" at 249.469,163.447 h1.52
  text "Bottom Layer" at 259.88,163.447 h1.52
  text "CF-004" at 293.653,163.447 h1.52
  text "1.38mil" at 308.889,163.447 h1.52
  text "Bottom Surface Finish" at 259.88,160.399 h1.52
  text "PbSn" at 293.653,160.399 h1.52
  text "0.79mil" at 308.889,160.399 h1.52
  text "Bottom Solder" at 259.88,157.351 h1.52
  text "SM-001" at 293.653,157.351 h1.52
  text "1.00mil" at 308.889,157.351 h1.52
  text "4" at 325.395,157.351 h1.52
  text "Bottom Overlay" at 259.88,154.303 h1.52
  text ".Layer_Name" at 14.656,-21.806 h1.52
M13 Component Bodies Top:
  text ".Layer_Name" at 14.656,-21.806 h1.52
M14 Component Bodies Bottom:
  text ".Layer_Name" at 14.656,-21.806 h1.52
M15 Courtyards Top:
  text ".Layer_Name" at 14.656,-21.806 h1.52
M16 Courtyards Bottom:
  text ".Layer_Name" at 14.656,-21.806 h1.52
Drill Drawing:
  circle w0.254: c136.236,80.425 r0.701
  lines w0.254: 135.535,67.458 135.886,67.458 136.236,67.107 136.587,67.458 136.937,67.458 136.587,67.808 136.937,68.159 136.587,68.159 136.236,68.509 135.886,68.159 135.535,68.159 135.886,67.808 135.535,67.458 ; 135.535,71.663 136.937,71.663 136.236,70.261 135.535,71.663 ; 135.535,73.415 136.236,73.766 136.937,73.415 136.587,74.116 136.937,74.817 136.236,74.467 135.535,74.817 135.886,74.116 135.535,73.415 ; 135.535,76.92 135.886,76.92 135.886,76.57 136.587,76.57 136.587,76.92 136.937,76.92 136.937,77.621 136.587,77.621 136.587,77.971 135.886,77.971 135.886,77.621 135.535,77.621 135.535,76.92 ; 135.535,82.878 136.937,82.878 136.937,84.279 135.535,84.279 135.535,82.878
  lines w0.305: 134.264,66.161 216.32,66.161 ; 134.264,85.086 216.32,85.086 ; 142.846,63.007 142.846,88.24 ; 151.279,63.007 151.279,88.24 ; 167.447,63.007 167.447,88.24 ; 174.029,63.007 174.029,88.24 ; 183.558,63.007 183.558,88.24 ; 201.932,63.007 201.932,88.24 ; 134.264,63.007 216.32,63.007 216.32,88.24 134.264,88.24 134.264,63.007
  text "Symbol" at 136.157,86.032 h1.83
  text "Quantity" at 143.792,86.032 h1.83
  text "Finished Hole Size" at 152.225,86.032 h1.83
  text "Plated" at 168.394,86.032 h1.83
  text "Hole Type" at 174.975,86.032 h1.83
  text "Drill Layer Pair" at 184.504,86.032 h1.83
  text "Hole Tolerance" at 202.878,86.032 h1.83
  text "5" at 143.792,82.878 h1.52
  text "7.87mil (0.200mm)" at 152.225,82.878 h1.52
  text "PTH" at 168.394,82.878 h1.52
  text "Round" at 174.975,82.878 h1.52
  text "Top Layer - Bottom Layer" at 184.504,82.878 h1.52
  text "48" at 143.792,79.724 h1.52
  text "12.60mil (0.320mm)" at 152.225,79.724 h1.52
  text "PTH" at 168.394,79.724 h1.52
  text "Round" at 174.975,79.724 h1.52
  text "Top Layer - Bottom Layer" at 184.504,79.724 h1.52
  text "8" at 143.792,76.57 h1.52
  text "23.62mil (0.600mm)" at 152.225,76.57 h1.52
  text "PTH" at 168.394,76.57 h1.52
  text "Round" at 174.975,76.57 h1.52
  text "Top Layer - Bottom Layer" at 184.504,76.57 h1.52
  text "8" at 143.792,73.415 h1.52
  text "27.56mil (0.700mm)" at 152.225,73.415 h1.52
  text "PTH" at 168.394,73.415 h1.52
  text "Round" at 174.975,73.415 h1.52
  text "Top Layer - Bottom Layer" at 184.504,73.415 h1.52
  text "+/-1.97mil" at 202.878,73.415 h1.52
  text "16" at 143.792,70.261 h1.52
  text "27.56mil (0.700mm)" at 152.225,70.261 h1.52
  text "PTH" at 168.394,70.261 h1.52
  text "Round" at 174.975,70.261 h1.52
  text "Top Layer - Bottom Layer" at 184.504,70.261 h1.52
  text "6" at 143.792,67.107 h1.52
  text "29.53mil (0.750mm)" at 152.225,67.107 h1.52
  text "PTH" at 168.394,67.107 h1.52
  text "Round" at 174.975,67.107 h1.52
  text "Top Layer - Bottom Layer" at 184.504,67.107 h1.52
  text "91 Total" at 143.792,63.953 h1.52
  text ".Layer_Name" at 14.656,-21.806 h1.52
M17 Embedded Cavity:
  text ".Layer_Name" at 14.656,-21.806 h1.52
M18 Embedded Assembly:
  text ".Layer_Name" at 14.656,-21.806 h1.52
M19 Embedded Keepout:
  text ".Layer_Name" at 14.656,-21.806 h1.52

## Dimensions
0,-10.16 to 25.4,-10.16 on M2 Board Dimensions
0,0 to 0,30 on M2 Board Dimensions
0,0 to 35,0 on M2 Board Dimensions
